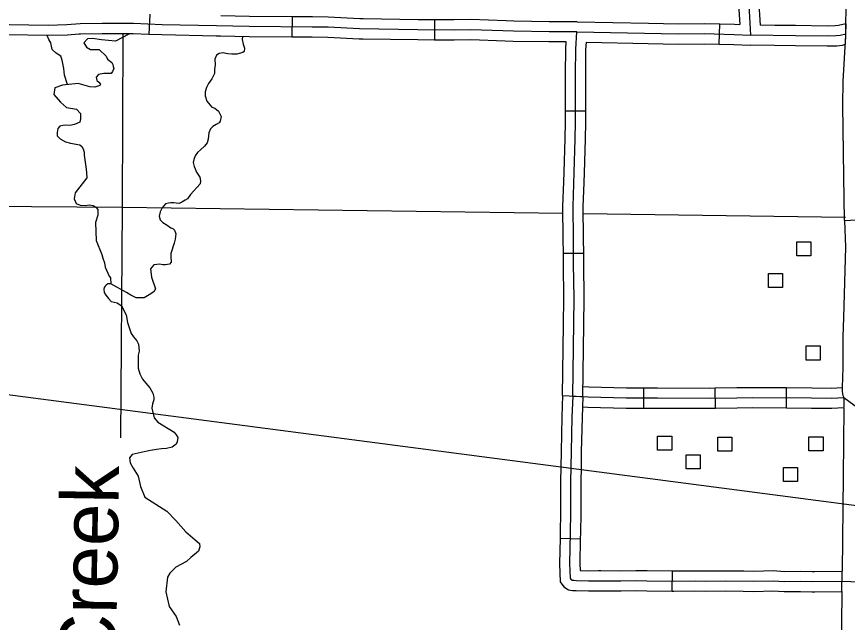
# Model space of a CAD drawing. Extents: x 61396 to 64680, y 55472 to 57605.
# Drawn here: x 62426.4 to 62618.7, y 56115 to 56255.3 of the extents above; entities that cross this region are included whole.
import ezdxf

# ---------------------------------------------------------------- set-up
doc = ezdxf.new("R2010")
doc.units = 0
for name, color, linetype in [('32', 7, 'Continuous'), ('33', 7, 'Continuous'), ('34', 7, 'Continuous'), ('35', 7, 'Continuous'), ('45', 7, 'Continuous'), ('5', 7, 'Continuous'), ('56', 7, 'Continuous'), ('6', 7, 'Continuous'), ('Default', 7, 'Continuous')]:
    doc.layers.add(name, color=color, linetype=linetype)

msp = doc.modelspace()

# ---------------------------------------------------------------- linework, layer by layer
at = {"layer": '32'}
for p, q in [((62571.62, 56164.66), (62571.62, 56169.35)), ((62588.16, 56164.63), (62588.08, 56169.32)), ((62604.6, 56164.71), (62604.64, 56169.4))]:
    msp.add_line(p, q, dxfattribs=at)
for points in [[(62557.5, 56169.66), (62558.85, 56169.58), (62567.55, 56169.35), (62571.62, 56169.35)], [(62571.62, 56169.35), (62574.75, 56169.35), (62586.91, 56169.29), (62588.08, 56169.32)], [(62588.08, 56169.32), (62593.09, 56169.41), (62596.82, 56169.46), (62604.64, 56169.4)], [(62604.64, 56169.4), (62610.45, 56169.35), (62615.04, 56169.29), (62617.53, 56169.43)], [(62555.13, 56167.45), (62558.75, 56167.23), (62567.52, 56167.01), (62574.74, 56167.01), (62586.92, 56166.95), (62593.13, 56167.06), (62596.83, 56167.12), (62610.43, 56167.01), (62615.09, 56166.95), (62617.9, 56167.11)], [(62617.88, 56167.12), (62617.86, 56164.76)], [(62557.38, 56164.97), (62558.65, 56164.89), (62567.49, 56164.66), (62571.62, 56164.66)], [(62571.62, 56164.66), (62574.74, 56164.66), (62586.94, 56164.61), (62588.16, 56164.63)], [(62588.16, 56164.63), (62593.17, 56164.72), (62596.83, 56164.78), (62604.6, 56164.71)], [(62604.6, 56164.71), (62610.4, 56164.66), (62615.14, 56164.61), (62617.86, 56164.76)]]:
    msp.add_lwpolyline(points, dxfattribs=at)
at = {"layer": '33'}
for points in [[(62618.36, 56251.26), (62618.43, 56259.5), (62618.45, 56261.6)], [(62618.07, 56208.06), (62617.88, 56218.39), (62617.63, 56234.81), (62617.7, 56240.35), (62618.36, 56250.94), (62618.36, 56251.26)], [(62618.07, 56208.06), (62618.28, 56201.93), (62617.82, 56185.64), (62617.67, 56181.18), (62617.62, 56174.06), (62617.53, 56169.41), (62617.51, 56168.57), (62617.55, 56167.94), (62617.68, 56167.54), (62617.9, 56167.11)], [(62618.07, 56208.06), (62620.84, 56208.26), (62627.26, 56208.26), (62631.69, 56208.16), (62638.73, 56207.92), (62646.35, 56208), (62650.56, 56208.02), (62654.11, 56207.81), (62655.57, 56207.7), (62658.51, 56207.62), (62660.83, 56207.65), (62672.64, 56207.84), (62676.45, 56207.84), (62682.34, 56207.54), (62691.51, 56207.52), (62698.07, 56207.49), (62710.8, 56207.23), (62716.75, 56206.98), (62722.53, 56206.75), (62727.57, 56206.72), (62730.31, 56206.66), (62732.93, 56206.72), (62736.7, 56206.82)], [(62617.9, 56167.11), (62620.17, 56165.43), (62623.77, 56162.6), (62625.9, 56160.95), (62628.3, 56159.24), (62632.09, 56156.34), (62637.98, 56151.65), (62640.22, 56149.86), (62641.98, 56148.1)]]:
    msp.add_lwpolyline(points, dxfattribs=at)
at = {"layer": '34'}
msp.add_lwpolyline([(62617.47, 56124.55), (62619.47, 56124.49), (62625.73, 56124.34), (62633.66, 56124.43), (62634.03, 56124.67), (62634.15, 56124.97), (62634.21, 56125.58), (62634.27, 56126.52), (62634.6, 56127.43), (62636, 56131.87), (62636.58, 56133.57), (62638.37, 56139.49), (62640.38, 56145.27), (62641.98, 56148.1)], dxfattribs=at)
at = {"layer": '35'}
for points in [[(62438.18, 56239.56), (62437.54, 56241.78), (62437.36, 56243.3), (62437.01, 56245.23), (62436.66, 56246.11), (62435.55, 56246.87), (62434.67, 56247.69), (62434.32, 56249.27), (62433.91, 56250.03), (62433.48, 56250.95)], [(62452.63, 56251.34), (62452.38, 56251.21), (62449.34, 56249.59), (62446.09, 56249.91), (62444.01, 56250.2), (62442.82, 56250.17), (62442.02, 56249.27), (62442.59, 56248.24), (62443.53, 56247.67), (62445.52, 56247.67), (62447.19, 56246.16), (62447.48, 56245.47), (62448.43, 56244.68), (62448.68, 56244.22), (62448.8, 56243.77), (62448.93, 56243.3), (62448.64, 56242.56), (62448.31, 56242.15), (62446.6, 56242.11), (62445.35, 56241.94), (62444.81, 56241.3), (62445, 56240.53), (62445.01, 56240.51)], [(62478.72, 56250.69), (62478.67, 56250.03), (62478.83, 56248.94), (62479.14, 56248.01), (62479.07, 56247.22), (62478.8, 56246.96), (62477.43, 56246.6), (62476.27, 56246.63), (62475.33, 56246.66), (62474.89, 56246.8), (62474.23, 56246.88), (62473.29, 56246.75), (62472.68, 56246.39), (62472.3, 56245.47), (62472.37, 56244.12), (62472.24, 56243.08), (62472.24, 56242.17), (62471.62, 56240.86), (62470.87, 56239.8), (62470.34, 56238.88), (62470.06, 56237.86), (62470.05, 56236.98), (62470.43, 56235.74), (62471.6, 56234.37), (62472.33, 56234.11), (62473.17, 56233.44), (62473.57, 56232.64), (62473.74, 56232.17), (62473.55, 56231.07), (62473.28, 56230.72), (62472.64, 56230.32), (62471.83, 56229.85), (62471.32, 56229.34), (62470.88, 56228.41), (62470.76, 56226.96), (62470.51, 56226.11), (62469.94, 56225.34), (62468.99, 56224.43), (62468.29, 56223.81), (62467.75, 56223.04), (62467.46, 56222.25), (62467.3, 56221.49), (62467.51, 56220.61), (62467.75, 56220.03), (62468.05, 56219.31), (62468.38, 56218.79), (62468.84, 56218.12), (62469.02, 56217.3), (62468.89, 56216.61), (62466.65, 56214.09), (62465.96, 56213.13), (62465.43, 56212.8), (62464.7, 56212.37), (62464.08, 56212.06), (62463.33, 56212.1), (62462.85, 56212.15), (62462.16, 56212.19), (62461.6, 56212.11), (62460.89, 56211.93), (62460.1, 56211.03), (62459.66, 56210.1), (62459.41, 56209.12), (62459.62, 56208.28), (62460.27, 56207.67), (62461.26, 56206.98), (62462.09, 56206.38), (62462.6, 56206.21), (62462.99, 56205.85), (62463.26, 56204.98), (62463.14, 56203.81), (62462.89, 56202.83), (62462.15, 56200.48), (62462.11, 56199.51), (62462.2, 56198.7), (62462.21, 56198.48)], [(62445, 56240.53), (62445.42, 56240.16), (62445.88, 56239.7), (62445.69, 56239.33), (62444.53, 56239), (62443.37, 56239.06), (62440.7, 56239.82), (62437.08, 56239.44), (62435.31, 56238.82), (62435.07, 56237.29), (62436.6, 56235.53), (62437.94, 56234.24), (62440.32, 56233.86), (62441.23, 56232.86), (62441.23, 56231.62), (62441.04, 56230.85), (62439.84, 56230.34), (62438.75, 56230.12), (62437.75, 56230.18), (62437.09, 56230.13), (62436.41, 56229.92), (62435.96, 56229.37), (62435.83, 56228.45), (62435.82, 56227.67), (62436.5, 56226.97), (62437.74, 56226.29), (62438.88, 56225.98), (62440.23, 56225.77), (62441.08, 56225.58), (62441.56, 56225.22), (62441.86, 56224.69)], [(62441.86, 56224.69), (62442.07, 56223.95), (62442.06, 56223.19), (62442.54, 56220.01), (62442.63, 56219.1), (62442.66, 56217.97), (62439.95, 56214.52), (62439.75, 56213.12), (62440.2, 56212.02), (62441.1, 56211.61), (62442.26, 56211.56), (62443.31, 56211.76), (62444.16, 56211.56), (62444.76, 56211.21), (62445.21, 56210.61), (62445.26, 56209.31), (62444.66, 56207.65), (62444.86, 56203.44), (62446.18, 56200.19), (62446.4, 56199.35), (62446.74, 56198.27), (62446.96, 56197.27), (62447.87, 56195.2), (62448.13, 56194.8), (62448.27, 56193.42)], [(62462.21, 56198.48), (62461.85, 56197.99), (62461.35, 56197.88), (62460.85, 56197.84), (62460.29, 56197.85), (62459.53, 56197.98), (62458.9, 56197.93), (62458.2, 56197.83), (62457.42, 56196.9), (62457.63, 56194.95), (62458.54, 56192.27), (62458.21, 56191.6), (62457.09, 56190.9), (62455.93, 56190.2), (62454.11, 56190.2), (62452.87, 56190.82), (62451.88, 56191.44), (62448.27, 56193.42), (62447.55, 56193.43), (62447.12, 56193.16), (62446.91, 56192.87), (62446.73, 56192.55), (62446.58, 56192.2), (62446.73, 56191.46), (62447.06, 56190.81), (62447.68, 56190.04), (62448.33, 56189.37), (62449.67, 56189.06), (62450.73, 56188.31), (62451.78, 56186.25), (62452.08, 56184.45), (62452.46, 56183.29), (62452.94, 56181.96), (62453.47, 56181.19), (62454.28, 56180.27), (62454.65, 56179.5), (62454.76, 56177.81), (62454.57, 56176.89), (62454.6, 56173.88), (62454.98, 56172.58), (62455.55, 56171.34), (62456.3, 56170.45), (62457.27, 56169.32), (62457.97, 56168.09), (62458.18, 56167.22), (62458.2, 56166.59), (62457.89, 56165.64), (62457.73, 56164.63), (62458.24, 56162.39), (62459.12, 56161.38), (62460.52, 56160.54), (62461.54, 56159.95), (62462.3, 56159.5), (62462.88, 56159.11), (62463.37, 56158.5), (62463.73, 56157.88), (62463.61, 56156.88), (62463.37, 56156.34), (62462.42, 56155.65), (62461.15, 56155.32), (62459.93, 56155.22), (62458.78, 56155.06), (62457.44, 56154.83), (62456.63, 56154.68), (62453.18, 56153.93), (62452.53, 56153.17), (62452.73, 56152.02), (62453.43, 56150.72), (62454.59, 56148.86), (62455.14, 56146.51), (62456.09, 56144.05), (62461.22, 56140.79), (62463.31, 56138.64), (62465.57, 56135.98), (62467.72, 56134.18), (62468.77, 56133.28), (62468.87, 56132.57), (62468.52, 56131.57), (62466.77, 56130.07), (62465.72, 56129.17), (62463.31, 56127.86)], [(62463.31, 56127.86), (62461.86, 56126.41), (62461.37, 56125.52), (62460.95, 56122.15), (62461.71, 56118.74), (62463.37, 56116.42), (62464.12, 56114.43)]]:
    msp.add_lwpolyline(points, dxfattribs=at)
at = {"layer": '45'}
for p, q in [((62457.25, 56255.88), (62457.06, 56251.2)), ((62490.17, 56255.26), (62490.12, 56250.57)), ((62523.15, 56254.56), (62523.12, 56249.87)), ((62589.05, 56248.93), (62589.18, 56253.62)), ((62618.38, 56253.67), (62618.22, 56248.82)), ((62558.15, 56233.44), (62553.46, 56233.44)), ((62557.68, 56200.47), (62552.99, 56200.43)), ((62552.79, 56167.54), (62557.47, 56167.36)), ((62552.21, 56134.51), (62556.89, 56134.41)), ((62578.13, 56122.27), (62578.2, 56126.96))]:
    msp.add_line(p, q, dxfattribs=at)
for points in [[(62601.99, 56264.07), (62598.83, 56264.12), (62597.22, 56264.05), (62595.3, 56263.69), (62594.02, 56262.4), (62593.45, 56260.95), (62593.45, 56259.36), (62593.82, 56253.47)], [(62618.45, 56261.6), (62614.93, 56261.48), (62608.51, 56261.62), (62598.86, 56261.78), (62597.49, 56261.71), (62596.45, 56261.52), (62596.02, 56261.09), (62595.8, 56260.51), (62595.8, 56259.43), (62596.32, 56251.01)], [(62601.91, 56259.38), (62598.9, 56259.43), (62598.15, 56259.4), (62598.53, 56253.32)], [(62490.17, 56255.26), (62480.3, 56255.35), (62473.69, 56255.47)], [(62556.12, 56251.79), (62549.66, 56251.77), (62541.42, 56251.92), (62531.55, 56252.28), (62527.69, 56252.19), (62519.32, 56252.24), (62505.82, 56252.46), (62498.5, 56252.83), (62494.86, 56252.87), (62480.27, 56253.01), (62472.68, 56253.14), (62460.09, 56253.42), (62453.45, 56253.69), (62446.22, 56253.69), (62441.13, 56253.6), (62438.09, 56253.37), (62433.77, 56253.28), (62420.22, 56253.46), (62412.54, 56253.51), (62396.58, 56253.74), (62388.85, 56254.01)], [(62506.67, 56254.79), (62505.9, 56254.81), (62498.57, 56255.17), (62494.89, 56255.22), (62490.17, 56255.26)], [(62523.15, 56254.56), (62519.35, 56254.58), (62506.67, 56254.79)], [(62539.71, 56254.33), (62531.57, 56254.63), (62527.67, 56254.53), (62523.15, 56254.56)], [(62556.2, 56254.13), (62549.68, 56254.12), (62541.48, 56254.26), (62539.71, 56254.33)], [(62556.18, 56254.13), (62572.67, 56253.77)], [(62572.67, 56253.77), (62579.59, 56253.62), (62585.61, 56253.71), (62589.18, 56253.62)], [(62589.18, 56253.62), (62592.61, 56253.53), (62593.82, 56253.47)], [(62618.38, 56253.67), (62616.62, 56253.27), (62615.9, 56253.16), (62614.03, 56253.12), (62606.73, 56253.21), (62601.93, 56253.28)], [(62555.13, 56167.45), (62555.44, 56190.05), (62555.35, 56198.11), (62555.3, 56203.9), (62555.21, 56211.3), (62555.5, 56219.21), (62555.72, 56226.94), (62555.81, 56230.9), (62555.81, 56242.06), (62555.86, 56247.73), (62556.12, 56251.79)], [(62556.12, 56251.79), (62579.58, 56251.28), (62585.6, 56251.37), (62592.53, 56251.19), (62596.32, 56251.01)], [(62601.93, 56253.28), (62598.53, 56253.32)], [(62440.83, 56251.23), (62438.2, 56251.03), (62433.78, 56250.94), (62424.13, 56251.07)], [(62457.06, 56251.2), (62453.4, 56251.35), (62446.24, 56251.35), (62441.24, 56251.26), (62440.83, 56251.23)], [(62473.6, 56250.78), (62472.63, 56250.8), (62460.01, 56251.07), (62457.06, 56251.2)], [(62490.12, 56250.57), (62480.24, 56250.66), (62473.6, 56250.78)], [(62506.6, 56250.11), (62505.74, 56250.12), (62498.43, 56250.48), (62494.84, 56250.53), (62490.12, 56250.57)], [(62523.12, 56249.87), (62519.3, 56249.89), (62506.6, 56250.11)], [(62539.54, 56249.64), (62531.54, 56249.94), (62527.71, 56249.85), (62523.12, 56249.87)], [(62553.62, 56249.44), (62549.64, 56249.43), (62541.35, 56249.57), (62539.54, 56249.64)], [(62618.36, 56251.26), (62617.05, 56250.96), (62616.09, 56250.82), (62614.04, 56250.78), (62606.7, 56250.87), (62596.32, 56251.01)], [(62553.46, 56233.44), (62553.46, 56242.07), (62553.52, 56247.82), (62553.62, 56249.44)], [(62558.15, 56233.44), (62558.15, 56242.04), (62558.21, 56247.65), (62558.32, 56249.4)], [(62558.32, 56249.4), (62572.57, 56249.09)], [(62572.57, 56249.09), (62579.57, 56248.93), (62585.59, 56249.03), (62589.05, 56248.93)], [(62589.05, 56248.93), (62592.44, 56248.84), (62596.21, 56248.67)], [(62601.87, 56248.59), (62596.29, 56248.66)], [(62618.22, 56248.82), (62617.47, 56248.65), (62616.28, 56248.48), (62614.05, 56248.43), (62606.67, 56248.52), (62601.87, 56248.59)], [(62553.07, 56217.03), (62553.15, 56219.28), (62553.38, 56227), (62553.46, 56230.92), (62553.46, 56233.44)], [(62557.76, 56216.86), (62557.84, 56219.13), (62558.06, 56226.89), (62558.15, 56230.87), (62558.15, 56233.44)], [(62552.99, 56200.43), (62552.95, 56203.87), (62552.87, 56211.33), (62553.07, 56217.03)], [(62557.68, 56200.47), (62557.64, 56203.92), (62557.56, 56211.27), (62557.76, 56216.86)], [(62553.01, 56183.98), (62553.09, 56190.06), (62553.01, 56198.08), (62552.99, 56200.43)], [(62557.7, 56183.92), (62557.78, 56190.05), (62557.7, 56198.13), (62557.68, 56200.47)], [(62552.79, 56167.54), (62553.01, 56183.98)], [(62557.47, 56167.36), (62557.7, 56183.92)], [(62552.79, 56167.54), (62552.6, 56162.62), (62552.45, 56154.64), (62552.37, 56151.01)], [(62555.13, 56167.45), (62554.94, 56162.55), (62554.79, 56154.59), (62554.64, 56147.61), (62554.64, 56140.44), (62554.58, 56135.85), (62554.43, 56128.65), (62554.55, 56125.25), (62554.7, 56125.03), (62555, 56124.85), (62555.37, 56124.79), (62556.01, 56124.76), (62558.8, 56124.67), (62561.08, 56124.7), (62566.31, 56124.67), (62569.77, 56124.73), (62572.32, 56124.7), (62578.52, 56124.61), (62583.44, 56124.67), (62585.87, 56124.61), (62590.55, 56124.67), (62597.05, 56124.55), (62601.52, 56124.67), (62604.13, 56124.52), (62607.84, 56124.55), (62610.51, 56124.49), (62617.47, 56124.55)], [(62557.47, 56167.36), (62557.29, 56162.48), (62557.13, 56154.54), (62557.06, 56150.91)], [(62552.37, 56151.01), (62552.3, 56147.63), (62552.3, 56140.45), (62552.23, 56135.89), (62552.21, 56134.51)], [(62557.06, 56150.91), (62556.98, 56147.58), (62556.98, 56140.42), (62556.92, 56135.81), (62556.89, 56134.41)], [(62552.21, 56134.51), (62552.08, 56128.63), (62552.23, 56124.46), (62553.08, 56123.28), (62554.18, 56122.61), (62555.12, 56122.46), (62555.91, 56122.42), (62558.78, 56122.33), (62561.09, 56122.36), (62561.65, 56122.35)], [(62556.89, 56134.41), (62556.77, 56128.67), (62556.83, 56127.08), (62558.82, 56127.01), (62561.07, 56127.04), (62561.68, 56127.04)], [(62561.68, 56127.04), (62566.29, 56127.01), (62569.76, 56127.07), (62572.35, 56127.04), (62578.2, 56126.96)], [(62578.2, 56126.96), (62578.52, 56126.95), (62583.46, 56127.01), (62585.89, 56126.95), (62590.56, 56127.01), (62594.71, 56126.94)], [(62594.71, 56126.94), (62597.04, 56126.89), (62601.55, 56127.02), (62604.19, 56126.86), (62607.85, 56126.89), (62610.53, 56126.83), (62611.13, 56126.84)], [(62611.13, 56126.84), (62617.49, 56126.89)], [(62611.17, 56122.15), (62617.44, 56122.21), (62617.49, 56126.89)], [(62561.65, 56122.35), (62566.32, 56122.33), (62569.78, 56122.39), (62572.29, 56122.36), (62578.13, 56122.27)], [(62578.13, 56122.27), (62578.52, 56122.27), (62583.43, 56122.33), (62585.86, 56122.27), (62590.54, 56122.33), (62594.62, 56122.25)], [(62594.62, 56122.25), (62597.06, 56122.2), (62601.48, 56122.32), (62604.07, 56122.17), (62607.82, 56122.2), (62610.49, 56122.14), (62611.17, 56122.15)]]:
    msp.add_lwpolyline(points, dxfattribs=at)
at = {"layer": '5'}
for points in [[(62451.05, 56251.35), (62450.87, 56211.18)], [(62356.23, 56211.85), (62450.87, 56211.18)], [(62450.87, 56211.18), (62450.47, 56157.76)], [(62450.87, 56211.18), (62552.89, 56209.76)], [(62557.58, 56209.7), (62618.25, 56208.85)]]:
    msp.add_lwpolyline(points, dxfattribs=at)
at = {"layer": '56'}
for points in [[(62606.99, 56199.93), (62606.99, 56203.19), (62610.26, 56203.19), (62610.26, 56199.93)], [(62600.43, 56192.58), (62600.43, 56195.83), (62603.69, 56195.83), (62603.69, 56192.58)], [(62609.14, 56175.79), (62609.14, 56179.05), (62612.4, 56179.05), (62612.4, 56175.79)], [(62574.78, 56154.92), (62574.78, 56158.17), (62578.04, 56158.17), (62578.04, 56154.92)], [(62588.7, 56154.69), (62588.7, 56157.95), (62591.96, 56157.95), (62591.96, 56154.69)], [(62609.82, 56154.76), (62609.82, 56158.01), (62613.08, 56158.01), (62613.08, 56154.76)], [(62581.4, 56150.58), (62581.4, 56153.83), (62584.66, 56153.83), (62584.66, 56150.58)], [(62603.94, 56147.64), (62603.94, 56150.89), (62607.2, 56150.89), (62607.2, 56147.64)]]:
    msp.add_lwpolyline(points, close=True, dxfattribs=at)
at = {"layer": '6'}
for points in [[(62617.86, 56164.65), (62617.72, 56148.93), (62617.49, 56126.89)], [(62617.44, 56122.17), (62617.05, 56083.86), (62616.74, 56049.34)]]:
    msp.add_lwpolyline(points, dxfattribs=at)
at = {"layer": 'Default'}
msp.add_line((61966.56, 56227.72), (62759.13, 56124.03), dxfattribs=at)

# ---------------------------------------------------------------- texts
at = {"layer": '35'}
msp.add_text('Creek', height=13.2, rotation=89.061, dxfattribs=at).set_placement((62449.38, 56104.19))

doc.saveas('drawing.dxf')
